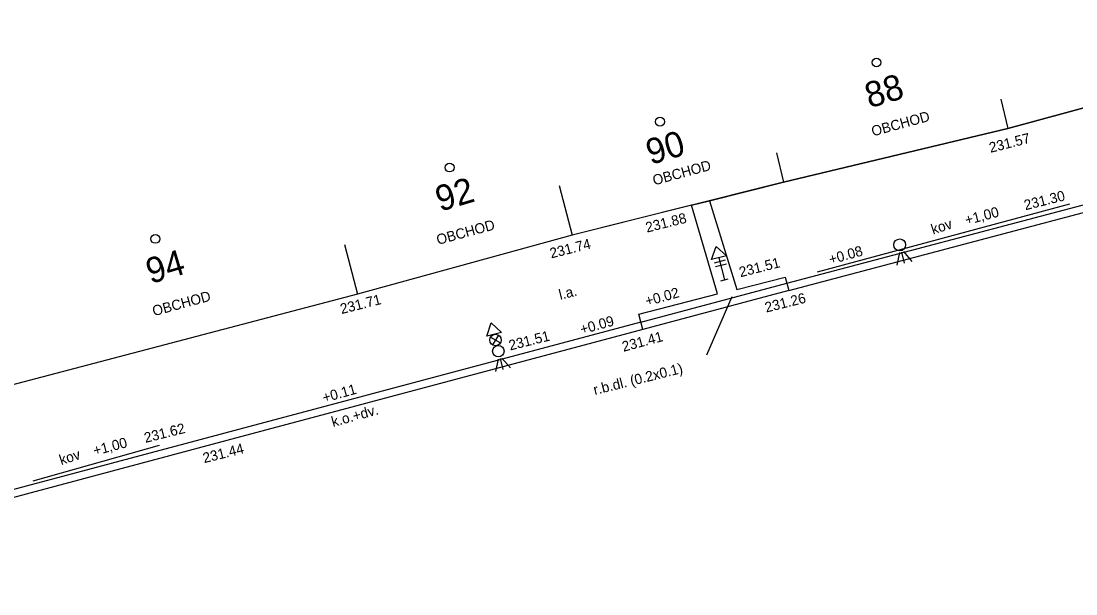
# Model space of a CAD drawing. Extents: x -598874 to -598664, y -1157512 to -1157364.
# Drawn here: x -598816.35 to -598774.93, y -1157458.21 to -1157435.72 of the extents above; entities that cross this region are included whole.
import ezdxf

# ---------------------------------------------------------------- set-up
doc = ezdxf.new("R2010")
doc.units = 0
for name, color, linetype in [('Vrstva 15', 7, 'Continuous'), ('Vrstva 22', 7, 'Continuous'), ('Vrstva 4', 7, 'Continuous'), ('Vrstva 43', 7, 'Continuous'), ('Vrstva 44', 7, 'Continuous'), ('Vrstva 49', 7, 'Continuous'), ('Vrstva 50', 7, 'Continuous'), ('Vrstva 58', 7, 'Continuous'), ('Vrstva 63', 7, 'Continuous'), ('Vrstva 7', 7, 'Continuous')]:
    doc.layers.add(name, color=color, linetype=linetype)

msp = doc.modelspace()

# ---------------------------------------------------------------- linework, layer by layer
at = {"layer": 'Vrstva 15'}
for centre in [(-598782.758, -1157437.343), (-598791.263, -1157439.668), (-598799.523, -1157441.468), (-598811.078, -1157444.268)]:
    msp.add_circle(centre, 0.175, dxfattribs=at)
at = {"layer": 'Vrstva 22'}
for p, q in [((-598775.186, -1157442.901), (-598785.086, -1157445.571)), ((-598810.926, -1157452.381), (-598815.886, -1157453.781))]:
    msp.add_line(p, q, dxfattribs=at)
at = {"layer": 'Vrstva 4'}
for p, q in [((-598768.749, -1157437.521), (-598777.596, -1157439.931)), ((-598777.871, -1157438.783), (-598777.596, -1157439.931)), ((-598777.596, -1157439.931), (-598786.407, -1157442.044)), ((-598786.682, -1157440.896), (-598786.407, -1157442.044)), ((-598795.216, -1157442.174), (-598794.706, -1157444.119)), ((-598786.407, -1157442.044), (-598794.706, -1157444.119)), ((-598794.706, -1157444.119), (-598803.145, -1157446.441)), ((-598803.655, -1157444.496), (-598803.145, -1157446.441)), ((-598803.145, -1157446.441), (-598818.404, -1157450.445))]:
    msp.add_line(p, q, dxfattribs=at)
at = {"layer": 'Vrstva 44'}
for p, q in [((-598788.944, -1157445.007), (-598788.725, -1157445.88)), ((-598781.849, -1157444.807), (-598781.958, -1157445.3)), ((-598781.777, -1157444.791), (-598781.667, -1157445.227)), ((-598781.704, -1157444.77), (-598781.376, -1157445.154)), ((-598789.12, -1157445.206), (-598788.686, -1157445.097)), ((-598789.084, -1157445.351), (-598788.654, -1157445.243)), ((-598788.87, -1157445.916), (-598788.579, -1157445.843)), ((-598797.914, -1157448.124), (-598797.526, -1157448.356)), ((-598797.603, -1157448.046), (-598797.836, -1157448.434)), ((-598797.61, -1157448.986), (-598797.719, -1157449.477)), ((-598797.537, -1157448.968), (-598797.428, -1157449.404)), ((-598797.465, -1157448.949), (-598797.137, -1157449.331))]:
    msp.add_line(p, q, dxfattribs=at)
for points in [[(-598789.235, -1157445.08), (-598789.054, -1157444.565), (-598788.653, -1157444.934)], [(-598797.481, -1157447.942), (-598798.065, -1157448.088), (-598797.886, -1157447.572)]]:
    msp.add_lwpolyline(points, close=True, dxfattribs=at)
for centre, radius in [((-598781.848, -1157444.504), 0.234), ((-598797.72, -1157448.24), 0.226), ((-598797.61, -1157448.677), 0.224)]:
    msp.add_circle(centre, radius, dxfattribs=at)
at = {"layer": 'Vrstva 49'}
msp.add_line((-598789.424, -1157448.817), (-598788.422, -1157446.531), dxfattribs=at)
at = {"layer": 'Vrstva 63'}
for p, q in [((-598786.282, -1157446.01), (-598747.42, -1157435.718)), ((-598777.596, -1157439.931), (-598768.749, -1157437.521)), ((-598786.407, -1157442.044), (-598777.596, -1157439.931)), ((-598789.316, -1157442.771), (-598786.407, -1157442.044)), ((-598790.022, -1157442.948), (-598794.706, -1157444.119)), ((-598790.022, -1157442.948), (-598789.316, -1157442.771)), ((-598794.706, -1157444.119), (-598803.145, -1157446.441)), ((-598792.014, -1157447.536), (-598786.282, -1157446.01)), ((-598803.145, -1157446.441), (-598818.404, -1157450.445)), ((-598792.014, -1157447.536), (-598808.343, -1157451.901)), ((-598808.343, -1157451.901), (-598830.969, -1157457.919))]:
    msp.add_line(p, q, dxfattribs=at)
at = {"layer": 'Vrstva 7'}
for p, q in [((-598786.205, -1157446.3), (-598747.343, -1157436.008)), ((-598790.022, -1157442.948), (-598789.316, -1157442.771)), ((-598788.996, -1157446.431), (-598790.022, -1157442.948)), ((-598789.316, -1157442.771), (-598788.246, -1157446.261)), ((-598788.246, -1157446.261), (-598786.346, -1157445.771)), ((-598786.346, -1157445.771), (-598786.205, -1157446.3)), ((-598786.205, -1157446.3), (-598791.937, -1157447.826)), ((-598792.097, -1157447.226), (-598788.996, -1157446.431)), ((-598791.937, -1157447.826), (-598792.097, -1157447.226)), ((-598791.937, -1157447.826), (-598808.266, -1157452.191)), ((-598808.266, -1157452.191), (-598830.892, -1157458.209))]:
    msp.add_line(p, q, dxfattribs=at)

# ---------------------------------------------------------------- texts
at = {"layer": 'Vrstva 43'}
for s, p in [('88', (-598783.036, -1157439.145)), ('90', (-598791.63, -1157441.369)), ('92', (-598799.9, -1157443.207)), ('94', (-598811.267, -1157446.044))]:
    msp.add_text(s, height=1, rotation=16.5472, dxfattribs=at).set_placement(p)
at = {"layer": 'Vrstva 49'}
for s, rotation, p in [('OBCHOD', 15.2612, (-598782.897, -1157440.246)), ('OBCHOD', 15.2612, (-598791.487, -1157442.171)), ('OBCHOD', 15.2612, (-598799.976, -1157444.507)), ('kov', 18.043, (-598780.54, -1157444.1)), ('l.a.', 14.0787, (-598795.177, -1157446.662)), ('OBCHOD', 15.2612, (-598811.133, -1157447.306)), ('r.b.dl. (0.2x0.1)', 14.0787, (-598793.822, -1157450.402)), ('k.o.+dv.', 15.596, (-598804.1, -1157451.658)), ('kov', 18.043, (-598814.774, -1157453.155))]:
    msp.add_text(s, height=0.4, rotation=rotation, dxfattribs=at).set_placement(p)
at = {"layer": 'Vrstva 50'}
for s, rotation, p in [('+1,00', 14.7294, (-598779.226, -1157443.73)), ('+0.08', 15.6364, (-598784.566, -1157445.277)), ('+0.02', 15.6364, (-598791.776, -1157446.914)), ('+0.09', 15.6364, (-598794.335, -1157448.025)), ('+0.11', 15.6364, (-598804.451, -1157450.706)), ('+1,00', 14.7294, (-598813.46, -1157452.785))]:
    msp.add_text(s, height=0.4, rotation=rotation, dxfattribs=at).set_placement(p)
at = {"layer": 'Vrstva 58'}
for s, rotation, p in [('231.57', 14.0787, (-598778.279, -1157440.89)), ('231.30', 14.0787, (-598776.911, -1157443.147)), ('231.88', 14.0787, (-598791.772, -1157444.024)), ('231.74', 14.0787, (-598795.532, -1157445.038)), ('231.51', 14.0787, (-598788.099, -1157445.776)), ('231.71', 14.0787, (-598803.764, -1157447.222)), ('231.26', 14.0787, (-598787.087, -1157447.164)), ('231.51', 14.0787, (-598797.143, -1157448.653)), ('231.41', 15.1567, (-598792.692, -1157448.704)), ('231.62', 14.0787, (-598811.463, -1157452.281)), ('231.44', 14.0787, (-598809.157, -1157453.076))]:
    msp.add_text(s, height=0.4, rotation=rotation, dxfattribs=at).set_placement(p)

doc.saveas('drawing.dxf')
